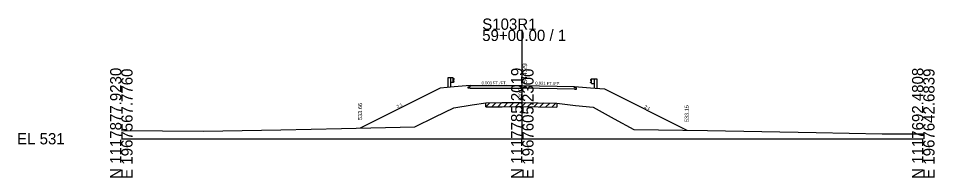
# Model space of a CAD drawing. Extents: x -26 to 203, y -10 to 12018.
# Drawn here: x -25.7 to 202.8, y 3990.3 to 4030 of the extents above; entities that cross this region are included whole.
import ezdxf

# ---------------------------------------------------------------- set-up
doc = ezdxf.new("R2010")
doc.units = 0
for name, color, linetype in [('Level 10', 7, 'Continuous'), ('Level 11', 7, 'Continuous'), ('Level 12', 7, 'Continuous'), ('Level 24', 7, 'Continuous'), ('Level 32', 7, 'Continuous'), ('Level 33', 7, 'Continuous'), ('Level 59', 7, 'Continuous'), ('Level 6', 7, 'Continuous'), ('Level 60', 7, 'Continuous'), ('Level 61', 7, 'Continuous'), ('Level 63', 7, 'Continuous'), ('Level 7', 7, 'Continuous')]:
    doc.layers.add(name, color=color, linetype=linetype)

msp = doc.modelspace()

# ---------------------------------------------------------------- linework, layer by layer
at = {"layer": 'Level 11'}
for p, q in [((87, 4012.95), (87, 4013.26)), ((86.5, 4012.95), (87, 4012.95)), ((86.5, 4012.59), (86.5, 4012.95)), ((87, 4012.59), (86.5, 4012.59)), ((113, 4012.71), (113, 4013.02)), ((113.5, 4012.7), (113, 4012.71)), ((113, 4012.35), (113.5, 4012.34)), ((113.5, 4012.34), (113.5, 4012.7))]:
    msp.add_line(p, q, dxfattribs=at)
at = {"layer": 'Level 12'}
for p in [(87, 4012.59), (113, 4012.35)]:
    msp.add_line(p, (100, 4012.62), dxfattribs=at)
at = {"layer": 'Level 24'}
for p, q in [((81.4, 4015.18), (81.4, 4012.79)), ((82.06, 4015.18), (81.4, 4015.18)), ((82.06, 4015.18), (82.06, 4012.85)), ((82.73, 4015.18), (82.06, 4015.18)), ((82.73, 4014.01), (82.06, 4014.01)), ((82.73, 4014.01), (82.73, 4015.18)), ((82.73, 4015.1), (83, 4014.9)), ((83, 4014.85), (82.73, 4014.65)), ((83, 4014.33), (82.73, 4014.53)), ((82.73, 4014.08), (83, 4014.28)), ((83, 4014.9), (83, 4014.85)), ((83, 4014.28), (83, 4014.33)), ((117.27, 4014.87), (117, 4014.67)), ((117, 4014.67), (117, 4014.62)), ((117, 4014.62), (117.27, 4014.42)), ((117, 4014.1), (117.27, 4014.3)), ((117, 4014.05), (117, 4014.1)), ((117.27, 4013.85), (117, 4014.05)), ((117.27, 4013.77), (117.27, 4014.94)), ((117.27, 4014.94), (117.94, 4014.94)), ((117.27, 4013.77), (117.94, 4013.77)), ((117.94, 4014.94), (117.94, 4012.61)), ((117.94, 4014.94), (118.6, 4014.94)), ((118.6, 4014.94), (118.6, 4012.56))]:
    msp.add_line(p, q, dxfattribs=at)
at = {"layer": 'Level 59'}
for p, q in [((87, 4013.26), (100, 4013.29)), ((100, 4013.29), (113, 4013.02))]:
    msp.add_line(p, q, dxfattribs=at)
at = {"layer": 'Level 6'}
for p, q in [((87, 4013.26), (83, 4012.93)), ((83, 4012.93), (79.5, 4012.64)), ((113, 4013.02), (117, 4012.69)), ((117, 4012.69), (120.5, 4012.4))]:
    msp.add_line(p, q, dxfattribs=at)
at = {"layer": 'Level 60'}
for p, q in [((87.49, 4008.44), (90.9, 4008.93)), ((90.9, 4008.93), (94.95, 4008.99)), ((94.95, 4008.99), (99.28, 4009.05)), ((99.28, 4009.05), (100, 4009.04)), ((100, 4009.04), (103.95, 4008.95)), ((103.95, 4008.95), (108.61, 4008.87)), ((108.61, 4008.87), (113.26, 4008.31)), ((78.26, 4005.45), (82.92, 4007.73)), ((82.92, 4007.73), (87.49, 4008.44)), ((113.26, 4008.31), (117.63, 4007.85)), ((117.63, 4007.85), (122.89, 4005)), ((73.2, 4002.97), (78.26, 4005.45)), ((122.89, 4005), (127.85, 4002.31)), ((0, 4002.04), (20.46, 4001.89)), ((20.46, 4001.89), (39.76, 4002.22)), ((39.76, 4002.22), (54.88, 4002.56)), ((54.88, 4002.56), (73.2, 4002.97)), ((127.85, 4002.31), (146.16, 4002.09)), ((146.16, 4002.09), (173.28, 4001.54)), ((173.28, 4001.54), (189.73, 4001.25)), ((189.73, 4001.25), (200, 4001.26))]:
    msp.add_line(p, q, dxfattribs=at)
at = {"layer": 'Level 61'}
for p, q in [((90.9, 4007.93), (91.92, 4008.94)), ((90.9, 4007.93), (90.9, 4008.93)), ((92.4, 4007.95), (93.42, 4008.97)), ((93.9, 4007.97), (94.92, 4008.99)), ((95.4, 4007.99), (96.42, 4009.01)), ((96.9, 4008.02), (97.92, 4009.03)), ((98.4, 4008.04), (99.41, 4009.05)), ((99.9, 4008.04), (100.88, 4009.02)), ((101.4, 4008), (102.38, 4008.98)), ((102.9, 4007.97), (103.88, 4008.95)), ((104.4, 4007.94), (105.39, 4008.92)), ((105.9, 4007.91), (106.89, 4008.9)), ((107.4, 4007.89), (108.39, 4008.87)), ((108.61, 4008.87), (108.61, 4007.87)), ((90.9, 4007.93), (94.95, 4007.99)), ((94.95, 4007.99), (99.28, 4008.05)), ((99.28, 4008.05), (100, 4008.04)), ((100, 4008.04), (103.95, 4007.95)), ((103.95, 4007.95), (108.61, 4007.87))]:
    msp.add_line(p, q, dxfattribs=at)
at = {"layer": 'Level 63'}
for p, q in [((100, 4000), (100, 4027.15)), ((0, 4000), (100, 4000)), ((100, 4000), (200, 4000))]:
    msp.add_line(p, q, dxfattribs=at)
at = {"layer": 'Level 7'}
for p, q in [((79.5, 4012.64), (59.55, 4002.66)), ((120.5, 4012.4), (141, 4002.15))]:
    msp.add_line(p, q, dxfattribs=at)

# ---------------------------------------------------------------- texts
at = {"layer": 'Level 10'}
msp.add_text(' 540.04', height=0.9, rotation=90, dxfattribs=at).set_placement((99.95, 4009.18))
at = {"layer": 'Level 32'}
for s, rotation, p in [('0.003 FT./FT.', 0.1467, (89.85, 4013.52)), ('0.021 FT./FT.', 358.8084, (103.22, 4013.48)), ('2:1', 26.5651, (68.91, 4007.62)), ('2:1', 333.4349, (130.36, 4007.75))]:
    msp.add_text(s, height=0.75, rotation=rotation, dxfattribs=at).set_placement(p)
at = {"layer": 'Level 33'}
for s, p in [('533.66', (60.05, 4004.66)), ('533.15', (141.5, 4004.15))]:
    msp.add_text(s, height=1, rotation=90, dxfattribs=at).set_placement(p)
at = {"layer": 'Level 59'}
msp.add_text(' 544.29', height=1.2, rotation=90, dxfattribs=at).set_placement((101.2, 4013.29))
at = {"layer": 'Level 63'}
for s, p in [('S103R1', (90, 4027.15)), ('59+00.00 / 1', (90, 4024.35)), ('EL 531', (-26, 3998.6))]:
    msp.add_text(s, height=2.8, dxfattribs=at).set_placement(p)
for s, p in [('N 1117877.9230', (0, 3990)), ('E 1967567.7760', (2.8, 3990)), ('N 1117785.2019', (100, 3990)), ('E 1967605.2300', (102.8, 3990)), ('N 1117692.4808', (200, 3990)), ('E 1967642.6839', (202.8, 3990))]:
    msp.add_text(s, height=2.8, rotation=90, dxfattribs=at).set_placement(p)

doc.saveas('drawing.dxf')
